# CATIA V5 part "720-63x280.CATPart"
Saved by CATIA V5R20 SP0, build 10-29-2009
Part number: 720-63x280
Definition: NONE
Nomenclature: 720-63x280
Source: Unknown
Description: 720-63x280
Bounding box of the stored display mesh (mm): x 0 to 280, y -31.5 to 31.5, z -31.5 to 31.5
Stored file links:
  C:\Users\Utente\Desktop\IO LAVORO\3D X SITO CF\X SITO\720\720-63x280.CATPart
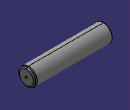
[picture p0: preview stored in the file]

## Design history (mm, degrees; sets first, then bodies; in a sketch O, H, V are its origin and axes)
Body1 "720-63x280" (main body)
  Solid1: solid without history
